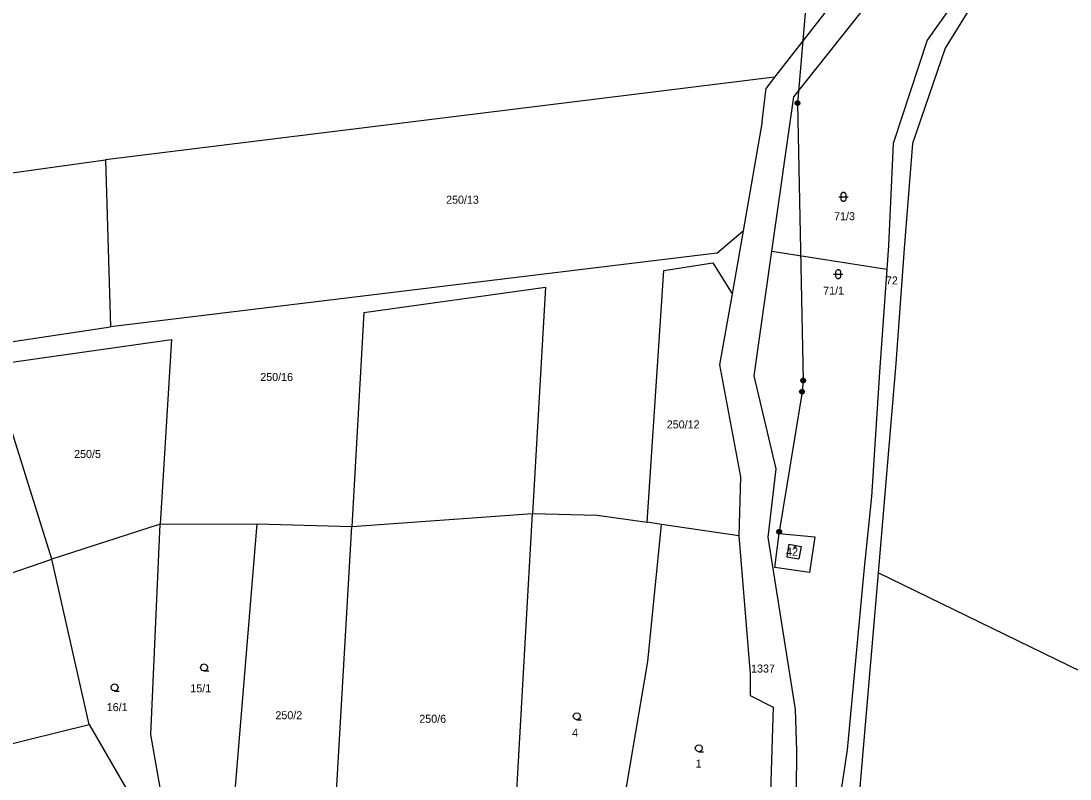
# Model space of a CAD drawing. Extents: x -845995 to -842497, y -1063614 to -1059680.
# Drawn here: x -844541.5 to -844318.8, y -1061366.9 to -1061205.9 of the extents above; entities that cross this region are included whole.
import ezdxf

# ---------------------------------------------------------------- set-up
doc = ezdxf.new("R2010")
doc.units = 0
for name, color, linetype in [('KN_HRANICE', 7, 'Continuous'), ('KN_KULTURY', 7, 'Continuous'), ('KN_PARCELY', 7, 'Continuous'), ('KN_SLUCKY', 7, 'Continuous'), ('KN_STAVEBNI', 7, 'Continuous'), ('KN_VEDENI', 7, 'Continuous')]:
    doc.layers.add(name, color=color, linetype=linetype)

# ---------------------------------------------------------------- blocks, each defined once
blk = doc.blocks.new('304')
blk.add_lwpolyline([(0, 0), (-0.38, 0.1), (-0.65, 0.37), (-0.75, 0.74), (-0.65, 1.11), (-0.38, 1.38), (-0.01, 1.48), (0.36, 1.38), (0.63, 1.11), (0.73, 0.73), (0.63, 0.35), (0.36, 0.08), (-0.02, -0.02), (0.98, -0.02)])
blk = doc.blocks.new('316')
for points in [[(-1, 1), (0.27, 1), (1, 1)], [(-0.5, 1.5), (-0.4, 1.79), (-0.15, 1.97), (0.16, 1.97), (0.41, 1.79), (0.51, 1.5), (0.51, 0.5), (0.41, 0.21), (0.16, 0.03), (-0.15, 0.03), (-0.4, 0.21), (-0.5, 0.5), (-0.5, 1.5)]]:
    blk.add_lwpolyline(points)
blk = doc.blocks.new('601')
blk.add_lwpolyline([(-0.15, 0.48), (0.16, 0.48), (0.41, 0.3), (0.51, 0.01), (0.41, -0.28), (0.16, -0.46), (-0.15, -0.46), (-0.4, -0.28), (-0.5, 0.01), (-0.4, 0.3), (-0.15, 0.48), (-0.12, 0.44), (0.12, 0.44), (0.28, 0.36), (-0.28, 0.36), (-0.36, 0.28), (0.36, 0.28), (0.36, 0.2), (-0.36, 0.2), (-0.4, 0.12), (0.4, 0.12), (0.44, 0.04), (-0.44, 0.04), (-0.44, -0.04), (0.44, -0.04), (0.41, -0.12), (-0.4, -0.12), (-0.39, -0.2), (0.42, -0.2), (0.37, -0.28), (-0.35, -0.28), (-0.27, -0.36), (0.29, -0.36), (0.18, -0.44), (-0.16, -0.44)])
blk = doc.blocks.new('402')
blk.add_lwpolyline([(0.09, 0.15), (0.18, 0), (0.09, -0.15), (-0.09, -0.15), (-0.18, 0), (-0.09, 0.15), (0.09, 0.15)])

msp = doc.modelspace()

# ---------------------------------------------------------------- linework, layer by layer
at = {"layer": 'KN_HRANICE'}
for p, q in [((-844377.45, -1061221.98), (-844351.54, -1061189.47)), ((-844332.94, -1061191.52), (-844345.28, -1061211.64)), ((-844363.83, -1061194.99), (-844381.5, -1061217.84)), ((-844338.18, -1061194.58), (-844349.09, -1061209.93)), ((-844349.09, -1061209.93), (-844356.33, -1061231.92)), ((-844345.28, -1061211.64), (-844352.26, -1061231.88)), ((-844381.5, -1061217.84), (-844523.56, -1061235.4)), ((-844381.5, -1061217.84), (-844383.3, -1061220.16)), ((-844384.13, -1061227.2), (-844383.3, -1061220.16)), ((-844382.08, -1061254.79), (-844377.45, -1061221.98)), ((-844384.13, -1061227.2), (-844388.18, -1061250.45)), ((-844356.33, -1061231.92), (-844357.35, -1061253.58)), ((-844352.26, -1061231.88), (-844354.02, -1061254.23)), ((-844673.82, -1061256.03), (-844523.56, -1061235.4)), ((-844523.56, -1061235.4), (-844522.5, -1061270.83)), ((-844393.8, -1061255.17), (-844388.18, -1061250.45)), ((-844388.18, -1061250.45), (-844390.51, -1061263.85)), ((-844357.35, -1061253.58), (-844357.7, -1061258.58)), ((-844354.02, -1061254.23), (-844355.8, -1061278.6)), ((-844393.8, -1061255.17), (-844522.5, -1061270.83)), ((-844385.82, -1061281.23), (-844382.08, -1061254.79)), ((-844382.08, -1061254.79), (-844357.7, -1061258.58)), ((-844408.56, -1061312.3), (-844405.01, -1061258.87)), ((-844405.01, -1061258.87), (-844394.6, -1061257.22)), ((-844394.6, -1061257.22), (-844390.51, -1061263.85)), ((-844357.7, -1061258.58), (-844359.23, -1061280.44)), ((-844468.71, -1061267.83), (-844430.13, -1061262.42)), ((-844430.13, -1061262.42), (-844432.89, -1061310.51)), ((-844390.51, -1061263.85), (-844393.23, -1061278.9)), ((-844468.71, -1061267.83), (-844471.31, -1061313.26)), ((-844595.18, -1061281.72), (-844522.5, -1061270.83)), ((-844547.89, -1061278.94), (-844509.56, -1061273.56)), ((-844509.56, -1061273.56), (-844511.96, -1061312.74)), ((-844534.95, -1061320.21), (-844547.89, -1061278.94)), ((-844393.23, -1061278.9), (-844388.72, -1061302.67)), ((-844355.8, -1061278.6), (-844359.49, -1061323.11)), ((-844381.2, -1061300.98), (-844385.82, -1061281.23)), ((-844359.23, -1061280.44), (-844360.93, -1061306.9)), ((-844382.88, -1061315.51), (-844381.2, -1061300.98)), ((-844388.72, -1061302.67), (-844389.08, -1061315.26)), ((-844360.93, -1061306.9), (-844362.55, -1061322.76)), ((-844437.76, -1061395.7), (-844432.89, -1061310.51)), ((-844432.89, -1061310.51), (-844419.21, -1061310.86)), ((-844419.21, -1061310.86), (-844408.56, -1061312.3)), ((-844405.53, -1061312.84), (-844408.56, -1061312.3)), ((-844511.96, -1061312.74), (-844534.95, -1061320.21)), ((-844513.95, -1061357.42), (-844511.96, -1061312.74)), ((-844511.96, -1061312.74), (-844491.42, -1061312.67)), ((-844491.42, -1061312.67), (-844497.75, -1061388.86)), ((-844491.42, -1061312.67), (-844471.31, -1061313.26)), ((-844475.97, -1061394.54), (-844471.31, -1061313.26)), ((-844408.43, -1061341.94), (-844405.53, -1061312.84)), ((-844389.08, -1061315.26), (-844405.53, -1061312.84)), ((-844389.08, -1061315.26), (-844386.69, -1061344.57)), ((-844377.08, -1061352.12), (-844382.88, -1061315.51)), ((-844381.43, -1061321.93), (-844380.57, -1061314.74)), ((-844380.57, -1061314.74), (-844372.96, -1061315.44)), ((-844372.96, -1061315.44), (-844374.09, -1061323)), ((-844553.2, -1061326.42), (-844534.95, -1061320.21)), ((-844527.05, -1061355.32), (-844534.95, -1061320.21)), ((-844374.09, -1061323), (-844381.43, -1061321.93)), ((-844362.55, -1061322.76), (-844366.12, -1061360.65)), ((-844359.49, -1061323.11), (-844364.48, -1061381.09)), ((-844282.06, -1061360.88), (-844359.49, -1061323.11)), ((-844413.69, -1061373.1), (-844408.43, -1061341.94)), ((-844386.69, -1061344.57), (-844386.69, -1061349.14)), ((-844386.69, -1061349.14), (-844381.84, -1061351.65)), ((-844381.84, -1061351.65), (-844383.28, -1061400.88)), ((-844376.79, -1061360.87), (-844377.08, -1061352.12)), ((-844546.85, -1061360.21), (-844527.05, -1061355.32)), ((-844527.05, -1061355.32), (-844515.02, -1061376.12)), ((-844510.28, -1061378.35), (-844513.95, -1061357.42)), ((-844376.86, -1061369.32), (-844376.79, -1061360.87)), ((-844366.12, -1061360.65), (-844369.26, -1061381.41))]:
    msp.add_line(p, q, dxfattribs=at)
at = {"layer": 'KN_SLUCKY'}
for p, q in [((-844471.31, -1061313.26), (-844432.89, -1061310.51)), ((-844378.47, -1061317.03), (-844378.94, -1061319.66)), ((-844378.47, -1061317.03), (-844375.89, -1061317.52)), ((-844375.89, -1061317.52), (-844376.38, -1061320.13)), ((-844378.94, -1061319.66), (-844376.38, -1061320.13))]:
    msp.add_line(p, q, dxfattribs=at)
at = {"layer": 'KN_STAVEBNI'}
for p, q in [((-844378.47, -1061317.03), (-844378.94, -1061319.66)), ((-844378.47, -1061317.03), (-844375.89, -1061317.52)), ((-844375.89, -1061317.52), (-844376.38, -1061320.13)), ((-844378.94, -1061319.66), (-844376.38, -1061320.13))]:
    msp.add_line(p, q, dxfattribs=at)
at = {"layer": 'KN_VEDENI'}
for p, q in [((-844371.23, -1061159.54), (-844376.65, -1061223.34)), ((-844376.65, -1061223.34), (-844375.44, -1061282.25)), ((-844375.44, -1061282.25), (-844375.69, -1061284.63)), ((-844375.69, -1061284.63), (-844380.55, -1061314.36))]:
    msp.add_line(p, q, dxfattribs=at)

# ---------------------------------------------------------------- block references
at = {"layer": 'KN_KULTURY'}
for name, p in [('316', (-844366.87, -1061244.23)), ('316', (-844368, -1061260.65)), ('402', (-844377.18, -1061317.63)), ('304', (-844502.65, -1061343.92)), ('304', (-844521.63, -1061348.17)), ('304', (-844423.51, -1061354.28)), ('304', (-844397.6, -1061361.08))]:
    msp.add_blockref(name, p, dxfattribs=at)
at = {"layer": 'KN_VEDENI'}
for p in [(-844376.65, -1061223.34), (-844375.44, -1061282.25), (-844375.69, -1061284.63), (-844380.55, -1061314.36)]:
    msp.add_blockref('601', p, dxfattribs=at)

# ---------------------------------------------------------------- texts
at = {"layer": 'KN_PARCELY'}
for s, p in [('250/13', (-844451.26, -1061244.7)), ('71/3', (-844368.87, -1061248.2)), ('72', (-844357.87, -1061261.85)), ('71/1', (-844371.19, -1061264.01)), ('250/16', (-844490.72, -1061282.35)), ('250/12', (-844404.4, -1061292.42)), ('250/5', (-844530.25, -1061298.7)), ('42', (-844379.08, -1061319.46)), ('1337', (-844386.5, -1061344.27)), ('15/1', (-844505.57, -1061348.48)), ('16/1', (-844523.32, -1061352.47)), ('250/2', (-844487.5, -1061354.19)), ('250/6', (-844456.95, -1061354.94)), ('4', (-844424.5, -1061357.89)), ('1', (-844398.29, -1061364.45))]:
    msp.add_text(s, height=1.7, dxfattribs=at).set_placement(p)

doc.saveas('drawing.dxf')
